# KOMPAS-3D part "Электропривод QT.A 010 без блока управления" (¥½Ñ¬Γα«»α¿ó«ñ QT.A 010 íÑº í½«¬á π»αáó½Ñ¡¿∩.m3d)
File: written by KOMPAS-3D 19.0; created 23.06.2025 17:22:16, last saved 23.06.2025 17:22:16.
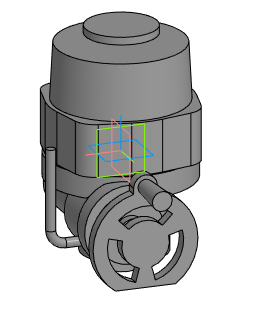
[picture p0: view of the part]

Document properties: Автор: Евгений; Полное имя файла: E:\Dendor Работа Сачек\3D для проектировщиков\3.5 Тип QT.А Электропривод\stp_Электропривод QT.A без блока управления\Электропривод QT.A 010 без блока управления.m3d

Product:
- Part/product: Электропривод QT.A 010 без блока управления

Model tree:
1. Операция без истории:1  (labels: Электропривод QT.A 010 без блока управления)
